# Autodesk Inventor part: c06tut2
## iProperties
Shininess: 77.0
Length Units: 11269
Angle Units: 11279
Time Units: 11290
Mass Units: 11283
Length Display Precision: 3
Angle Display Precision: 2
Created: 2001-12
Part Number: c06tut2
Document SubType Name: Modeling
Designer: Deepak Maini
Density: 1 g/cm^3
Density: 0.0
Volumn: 0.0
Area: 0.0
PropertySet Name: Model Information
Control State: 0
Master: False
Checked Out: False
Author: Deepak Maini
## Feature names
1. Extrusion1
2. Hole1
3. Extrusion2
4. Extrusion3
5. Extrusion4
6. Extrusion5
7. Hole2
8. Hole3
9. Hole4
